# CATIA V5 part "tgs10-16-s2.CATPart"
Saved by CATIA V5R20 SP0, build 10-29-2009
Part number: TGS10-16-S2
Revision: 1
Definition: design
Nomenclature: TGS10-16-S2
Source: made
Description: NOT SPECIFIED
Bounding box of the stored display mesh (mm): x -22 to 0.8, y 0 to 10, z -4 to 4
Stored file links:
  C:\Users\Raffaele\Desktop\3D X SITO CF\I-MOLD\TGS-S2\tgs10-s2.step\tgs10-16-s2.CATPart
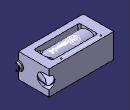
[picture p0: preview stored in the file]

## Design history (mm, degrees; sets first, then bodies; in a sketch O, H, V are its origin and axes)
Set1
  Line1 "LINE #4211": stored without definition
  DatumCurve1 "COMPOSITE_CURVE #4282"
  DatumCurve2 "COMPOSITE_CURVE #4333"
  DatumCurve3 "COMPOSITE_CURVE #4412"
  DatumCurve4 "COMPOSITE_CURVE #4455"
  DatumCurve5 "COMPOSITE_CURVE #4684"
  DatumCurve6 "COMPOSITE_CURVE #4826"
  DatumCurve7 "COMPOSITE_CURVE #4853"
  DatumCurve8 "COMPOSITE_CURVE #4911"
  DatumCurve9 "COMPOSITE_CURVE #4968"
  DatumCurve10 "COMPOSITE_CURVE #4997"
  DatumSurface1 "OPEN_SHELL #4201"
Body1 "MANIFOLD_SOLID_BREP #4202" (main body)
  Solid1: solid without history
